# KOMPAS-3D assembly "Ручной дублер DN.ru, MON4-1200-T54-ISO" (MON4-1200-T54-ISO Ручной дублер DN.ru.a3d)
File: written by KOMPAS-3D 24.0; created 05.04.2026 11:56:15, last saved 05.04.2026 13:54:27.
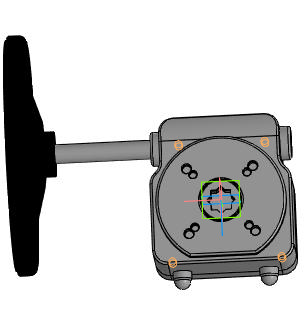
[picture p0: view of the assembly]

Document properties: Автор: R2D2; Полное имя файла: E:\Работа\Зайцев\Аксессуары для пневмоприводов\Ручной дублер DN.ru\MON4-1200-T54-ISO Ручной дублер DN.ru\исходные материалы\MON4-1200-T54-ISO Ручной дублер DN.ru.a3d

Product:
- Component [detail]: Деталь1  | qty 1  | pos. 1  | Масса: 35.407781; Автор: R2D2; additional columns: Типовые; source file: 3.m3d
- Component [detail]: Деталь1  | qty 1  | pos. 1  | Масса: 35.407781; Автор: R2D2; additional columns: Типовые; source file: 2.m3d
- Component [detail]: Деталь1  | qty 1  | pos. 1  | Масса: 35.407781; Автор: R2D2; additional columns: Типовые; source file: 1.m3d
- Component [detail]: Деталь 2  | qty 1  | pos. 2  | Масса: 6.906855; Автор: R2D2; additional columns: Типовые; source file: Деталь 2 Деталь 2.m3d
- Component [standard]: Hexagon socket head cap screw ISO 4762 - М12 x 20  | qty 4  | Материал: Не определено (density 0 kg/m3); Масса: 0.0321; Раздел спецификации: Стандартные изделия; Рассекать на разрезах: no
- Part/product: Ручной дублер DN.ru  | designation MON4-1200-T54-ISO
    Масса: 13.7
    Раздел спецификации: Прочие изделия
    Примечание: D290-00339

Referenced files in E:\Работа\Зайцев\Аксессуары для пневмоприводов\Ручной дублер DN.ru\MON4-1200-T54-ISO Ручной дублер DN.ru\исходные материалы\: 3.m3d, 2.m3d, 1.m3d, Деталь 2 Деталь 2.m3d
Referenced files in C:\Program Files\ASCON\KOMPAS-3D v24\Libs\PolynomLib\DATA\vault\Methods\Kompas\3D\: PLib_Screw_DIN_7984_1500.m3d
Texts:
  Hexagon socket head cap screw
  BOSimple***PART:d0712955-55fa-f496-1eba-993b7d03c8f4***SHORTLOC:A259_235BDFABBEFC4171[1,75;20;12;-;Undefined]
  Программные изделия  и базы данных
  MON4-1200-T54-ISO
  Деталь1 Деталь1
  Деталь 2 Деталь 2
  Hexagon socket head cap screw ISO 4762 - М12 x 20 (1)
  Hexagon socket head cap screw ISO 4762 - М12 x 20 (2)
  Hexagon socket head cap screw ISO 4762 - М12 x 20 (4)
  Hexagon socket head cap screw ISO 4762 - М12 x 20 (6)
  Ось Y.Начало координат
  Плоскость ZX.Начало координат
  Плоскость ZY.Начало координат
